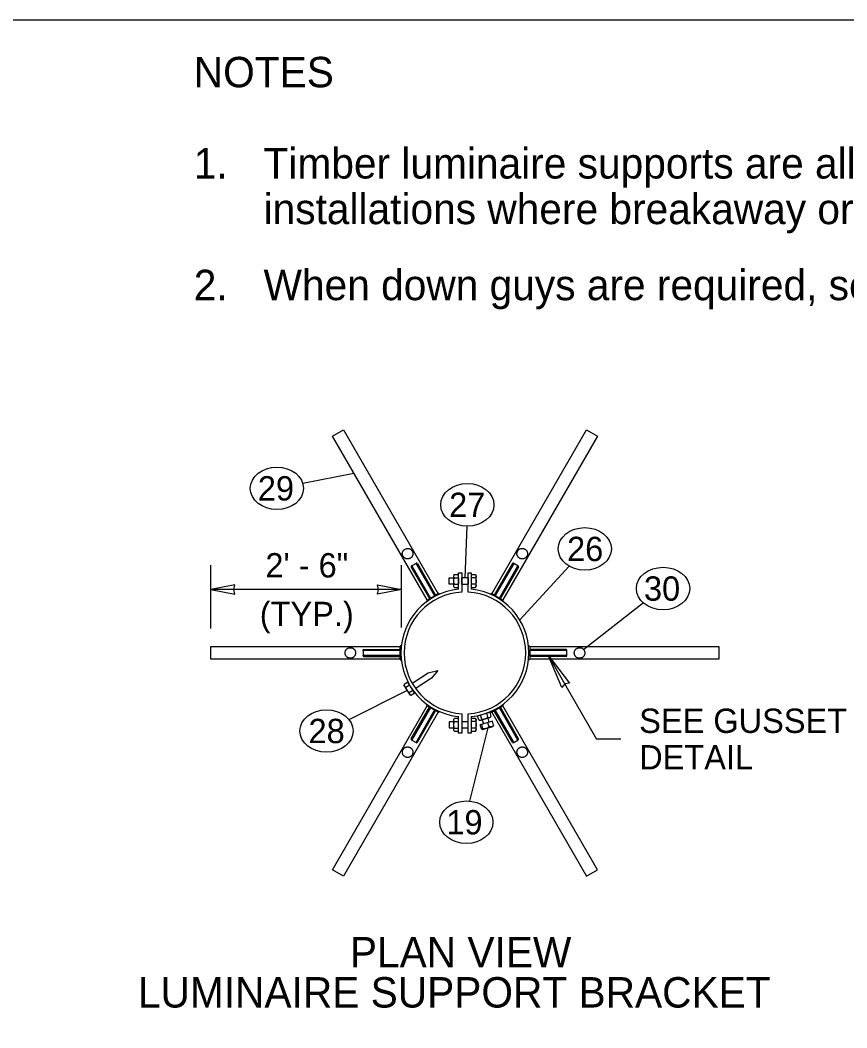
# Model space of a CAD drawing. Extents: x 99862 to 104211, y 98939 to 102076.
# Drawn here: x 102205 to 102749, y 101413 to 102076 of the extents above; entities that cross this region are included whole.
import ezdxf

# ---------------------------------------------------------------- set-up
doc = ezdxf.new("R2010")
doc.units = 0
for name, color, linetype in [('Level 1', 7, 'Continuous'), ('Level 15', 7, 'Continuous'), ('Level 2', 7, 'Continuous'), ('Level 20', 7, 'Continuous'), ('Level 3', 7, 'Continuous'), ('Level 4', 7, 'Continuous'), ('Level 7', 7, 'Continuous'), ('Level 9', 7, 'Continuous')]:
    doc.layers.add(name, color=color, linetype=linetype)

msp = doc.modelspace()

# ---------------------------------------------------------------- linework, layer by layer
at = {"layer": 'Level 1'}
msp.add_lwpolyline([(99862, 99999.5), (103151, 99999.5), (103151, 102075.5), (99862, 102075.5)], close=True, dxfattribs=at)
at = {"layer": 'Level 15'}
for p, q in [((102390.97, 101770.99), (102424.58, 101777.63)), ((102498.77, 101742.78), (102497.63, 101708.74)), ((102330.55, 101675.56), (102330.55, 101717.03)), ((102455.81, 101676.03), (102455.81, 101717.03)), ((102566.08, 101716.5), (102533.67, 101681.12)), ((102455.81, 101701.03), (102330.55, 101701.03)), ((102614.99, 101692.33), (102575.75, 101661.56)), ((102552.44, 101657.85), (102584.22, 101602.81)), ((102421.39, 101615.56), (102459.49, 101634.79)), ((102512.67, 101610.1), (102500.54, 101561.98)), ((102600.22, 101602.81), (102584.22, 101602.81))]:
    msp.add_line(p, q, dxfattribs=at)
for points in [[(102330.55, 101701.03), (102346.28, 101697.94), (102345.55, 101701.03), (102346.28, 101704.11)], [(102455.81, 101701.03), (102440.08, 101697.94), (102440.81, 101701.03), (102440.08, 101704.11)], [(102552.44, 101657.85), (102566.44, 101639.57), (102563.33, 101638.99), (102561.27, 101636.59)]]:
    msp.add_lwpolyline(points, close=True, dxfattribs=at)
at = {"layer": 'Level 2'}
for p, q in [((102493.48, 101701.28), (102493.48, 101712.14)), ((102493.48, 101712.14), (102495.55, 101712.14)), ((102493.48, 101708.76), (102493.48, 101704.61)), ((102495.55, 101712.14), (102495.55, 101699.35)), ((102495.55, 101704.61), (102495.55, 101708.76)), ((102499.7, 101699.35), (102499.7, 101712.14)), ((102499.7, 101712.14), (102501.78, 101712.14)), ((102499.7, 101708.76), (102499.7, 101704.61)), ((102501.78, 101712.14), (102501.78, 101701.28)), ((102493.48, 101704.59), (102493.48, 101704.61)), ((102495.55, 101704.61), (102495.55, 101704.59)), ((102495.55, 101704.61), (102495.55, 101704.59)), ((102493.48, 101606.67), (102493.48, 101617.54)), ((102495.55, 101619.46), (102495.55, 101606.67)), ((102499.7, 101606.67), (102499.7, 101619.46)), ((102501.78, 101617.54), (102501.78, 101606.67)), ((102495.55, 101606.67), (102493.48, 101606.67)), ((102501.78, 101606.67), (102499.7, 101606.67))]:
    msp.add_line(p, q, dxfattribs=at)
for radius, start, end in [(42.07, 95.66048, 264.33952), (42.07, 275.66048, 84.33952), (40, 92.97355, 267.02645), (40, 272.97355, 87.02645)]:
    msp.add_arc((102497.63, 101659.41), radius, start, end, dxfattribs=at)
at = {"layer": 'Level 20'}
for centre in [(102373.98, 101767.64), (102499.24, 101756.78), (102576.43, 101727.79), (102627.93, 101701.75), (102406.59, 101608.08), (102498.57, 101548.07)]:
    msp.add_ellipse(centre, major_axis=(-17.5, 0), ratio=0.8, dxfattribs=at)
at = {"layer": 'Level 3'}
for p, q in [((102465.46, 101718.24), (102462.76, 101716.68)), ((102462.77, 101716.67), (102474.98, 101695.52)), ((102477.68, 101697.07), (102465.46, 101718.24)), ((102529.79, 101718.23), (102517.58, 101697.07)), ((102520.27, 101695.52), (102532.49, 101716.68)), ((102532.49, 101716.68), (102529.8, 101718.24)), ((102455.03, 101660.96), (102430.6, 101660.96)), ((102430.6, 101660.96), (102430.6, 101657.85)), ((102564.65, 101660.96), (102540.22, 101660.96)), ((102564.66, 101657.85), (102564.66, 101660.96)), ((102430.6, 101657.85), (102455.03, 101657.85)), ((102540.22, 101657.85), (102564.66, 101657.85)), ((102474.98, 101623.3), (102462.76, 101602.13)), ((102465.46, 101600.58), (102477.68, 101621.74)), ((102517.58, 101621.74), (102529.8, 101600.58)), ((102532.49, 101602.14), (102520.27, 101623.3)), ((102462.76, 101602.13), (102465.46, 101600.58)), ((102529.8, 101600.58), (102532.49, 101602.13))]:
    msp.add_line(p, q, dxfattribs=at)
at = {"layer": 'Level 4'}
for p, q in [((102410.5, 101802.02), (102417.68, 101806.17)), ((102417.68, 101806.17), (102479.92, 101698.37)), ((102515.33, 101698.37), (102577.57, 101806.17)), ((102577.57, 101806.17), (102584.76, 101802.02)), ((102472.74, 101694.22), (102410.5, 101802.02)), ((102584.76, 101802.02), (102522.52, 101694.22)), ((102330.55, 101655.26), (102330.55, 101663.56)), ((102330.55, 101663.56), (102455.03, 101663.56)), ((102540.22, 101663.56), (102664.7, 101663.56)), ((102664.7, 101663.56), (102664.7, 101655.26)), ((102455.03, 101655.26), (102330.55, 101655.26)), ((102664.7, 101655.26), (102540.22, 101655.26)), ((102410.5, 101516.79), (102472.74, 101624.59)), ((102479.92, 101620.44), (102417.68, 101512.64)), ((102515.33, 101620.44), (102577.57, 101512.64)), ((102584.76, 101516.79), (102522.52, 101624.59)), ((102417.68, 101512.64), (102410.5, 101516.79)), ((102577.57, 101512.64), (102584.76, 101516.79))]:
    msp.add_line(p, q, dxfattribs=at)
for points in [[(102458.22, 101727.67), (102458, 101727.54), (102457.81, 101727.4), (102457.45, 101727.09), (102457.29, 101726.92), (102456.86, 101726.37), (102456.67, 101725.97), (102456.45, 101725.14), (102456.42, 101724.71), (102456.52, 101724.06), (102456.57, 101723.83), (102456.72, 101723.39), (102456.83, 101723.17), (102457.07, 101722.75), (102457.21, 101722.55), (102457.52, 101722.19), (102457.68, 101722.04), (102458.03, 101721.76), (102458.21, 101721.64), (102458.6, 101721.45), (102458.79, 101721.38), (102459.41, 101721.21), (102459.86, 101721.17), (102460.55, 101721.27), (102460.78, 101721.32), (102461.23, 101721.48), (102461.45, 101721.58), (102461.87, 101721.82), (102462.07, 101721.96), (102462.43, 101722.28), (102462.59, 101722.45), (102462.88, 101722.81), (102463, 101723.01), (102463.19, 101723.4), (102463.27, 101723.61), (102463.43, 101724.23), (102463.46, 101724.66), (102463.36, 101725.31), (102463.31, 101725.53), (102463.16, 101725.98), (102463.05, 101726.2), (102462.81, 101726.62), (102462.67, 101726.82), (102462.36, 101727.18), (102462.2, 101727.33), (102461.85, 101727.6), (102461.67, 101727.72), (102461.29, 101727.91), (102461.09, 101727.99), (102460.67, 101728.1), (102460.46, 101728.14), (102460.02, 101728.17), (102459.79, 101728.16), (102459.11, 101728.07), (102458.64, 101727.91), (102458.22, 101727.67)], [(102537.04, 101727.67), (102536.83, 101727.79), (102536.6, 101727.89), (102536.15, 101728.04), (102535.92, 101728.1), (102535.24, 101728.19), (102534.79, 101728.16), (102533.97, 101727.94), (102533.58, 101727.74), (102533.06, 101727.34), (102532.89, 101727.18), (102532.59, 101726.82), (102532.45, 101726.62), (102532.2, 101726.2), (102532.1, 101725.98), (102531.94, 101725.54), (102531.89, 101725.32), (102531.83, 101724.88), (102531.82, 101724.66), (102531.84, 101724.23), (102531.88, 101724.02), (102532.04, 101723.4), (102532.24, 101723), (102532.66, 101722.45), (102532.82, 101722.28), (102533.18, 101721.96), (102533.38, 101721.82), (102533.8, 101721.58), (102534.03, 101721.47), (102534.48, 101721.32), (102534.71, 101721.27), (102535.17, 101721.21), (102535.39, 101721.2), (102535.83, 101721.23), (102536.05, 101721.26), (102536.66, 101721.43), (102537.05, 101721.62), (102537.57, 101722.03), (102537.74, 101722.19), (102538.04, 101722.54), (102538.18, 101722.74), (102538.43, 101723.17), (102538.53, 101723.38), (102538.68, 101723.83), (102538.74, 101724.05), (102538.8, 101724.49), (102538.81, 101724.71), (102538.79, 101725.13), (102538.75, 101725.34), (102538.64, 101725.76), (102538.57, 101725.96), (102538.37, 101726.36), (102538.25, 101726.55), (102537.83, 101727.1), (102537.46, 101727.42), (102537.04, 101727.67)], [(102418.81, 101659.41), (102418.81, 101659.16), (102418.83, 101658.92), (102418.92, 101658.45), (102418.99, 101658.22), (102419.25, 101657.58), (102419.5, 101657.21), (102420.11, 101656.61), (102420.47, 101656.37), (102421.08, 101656.13), (102421.3, 101656.06), (102421.76, 101655.97), (102422.01, 101655.95), (102422.49, 101655.95), (102422.73, 101655.97), (102423.2, 101656.06), (102423.41, 101656.12), (102423.83, 101656.29), (102424.02, 101656.39), (102424.38, 101656.63), (102424.54, 101656.76), (102425, 101657.21), (102425.25, 101657.58), (102425.51, 101658.22), (102425.58, 101658.45), (102425.67, 101658.92), (102425.7, 101659.16), (102425.7, 101659.65), (102425.67, 101659.89), (102425.58, 101660.36), (102425.51, 101660.59), (102425.34, 101661.02), (102425.23, 101661.21), (102424.99, 101661.58), (102424.85, 101661.75), (102424.39, 101662.2), (102424.03, 101662.44), (102423.42, 101662.68), (102423.2, 101662.75), (102422.74, 101662.84), (102422.5, 101662.86), (102422.01, 101662.86), (102421.77, 101662.84), (102421.31, 101662.75), (102421.09, 101662.69), (102420.68, 101662.52), (102420.49, 101662.42), (102420.13, 101662.19), (102419.96, 101662.05), (102419.66, 101661.75), (102419.52, 101661.58), (102419.27, 101661.22), (102419.17, 101661.02), (102418.9, 101660.38), (102418.81, 101659.9), (102418.81, 101659.41)], [(102576.45, 101659.41), (102576.45, 101659.65), (102576.42, 101659.89), (102576.33, 101660.36), (102576.26, 101660.59), (102576, 101661.23), (102575.75, 101661.6), (102575.14, 101662.2), (102574.79, 101662.44), (102574.17, 101662.68), (102573.95, 101662.75), (102573.49, 101662.84), (102573.25, 101662.86), (102572.76, 101662.86), (102572.52, 101662.84), (102572.06, 101662.75), (102571.84, 101662.69), (102571.43, 101662.52), (102571.23, 101662.42), (102570.88, 101662.19), (102570.71, 101662.05), (102570.26, 101661.6), (102570, 101661.23), (102569.74, 101660.59), (102569.67, 101660.36), (102569.58, 101659.89), (102569.56, 101659.65), (102569.56, 101659.16), (102569.58, 101658.92), (102569.67, 101658.45), (102569.74, 101658.22), (102569.92, 101657.8), (102570.02, 101657.6), (102570.27, 101657.23), (102570.41, 101657.06), (102570.86, 101656.61), (102571.22, 101656.37), (102571.83, 101656.13), (102572.05, 101656.06), (102572.51, 101655.97), (102572.76, 101655.95), (102573.24, 101655.95), (102573.48, 101655.97), (102573.95, 101656.06), (102574.17, 101656.13), (102574.58, 101656.29), (102574.77, 101656.39), (102575.13, 101656.62), (102575.29, 101656.76), (102575.6, 101657.06), (102575.74, 101657.23), (102575.98, 101657.59), (102576.09, 101657.79), (102576.35, 101658.44), (102576.45, 101658.92), (102576.45, 101659.41)], [(102458.22, 101591.14), (102458.43, 101591.02), (102458.65, 101590.92), (102459.1, 101590.77), (102459.33, 101590.71), (102460.02, 101590.62), (102460.46, 101590.65), (102461.29, 101590.88), (102461.67, 101591.07), (102462.19, 101591.48), (102462.36, 101591.64), (102462.67, 101591.99), (102462.81, 101592.19), (102463.05, 101592.61), (102463.15, 101592.83), (102463.31, 101593.28), (102463.36, 101593.5), (102463.43, 101593.93), (102463.43, 101594.15), (102463.41, 101594.58), (102463.38, 101594.79), (102463.21, 101595.41), (102463.02, 101595.81), (102462.59, 101596.36), (102462.43, 101596.54), (102462.07, 101596.85), (102461.87, 101596.99), (102461.45, 101597.24), (102461.23, 101597.34), (102460.78, 101597.49), (102460.55, 101597.55), (102460.09, 101597.61), (102459.86, 101597.61), (102459.42, 101597.59), (102459.21, 101597.55), (102458.59, 101597.38), (102458.2, 101597.19), (102457.68, 101596.78), (102457.52, 101596.62), (102457.21, 101596.27), (102457.07, 101596.07), (102456.83, 101595.65), (102456.73, 101595.43), (102456.57, 101594.98), (102456.52, 101594.76), (102456.45, 101594.33), (102456.44, 101594.11), (102456.47, 101593.68), (102456.5, 101593.47), (102456.61, 101593.05), (102456.69, 101592.85), (102456.88, 101592.46), (102457, 101592.26), (102457.42, 101591.71), (102457.79, 101591.39), (102458.22, 101591.14)], [(102537.04, 101591.14), (102537.25, 101591.27), (102537.45, 101591.41), (102537.81, 101591.72), (102537.97, 101591.9), (102538.39, 101592.44), (102538.59, 101592.85), (102538.81, 101593.67), (102538.83, 101594.1), (102538.74, 101594.75), (102538.69, 101594.98), (102538.53, 101595.42), (102538.43, 101595.64), (102538.19, 101596.07), (102538.05, 101596.26), (102537.74, 101596.62), (102537.57, 101596.78), (102537.23, 101597.05), (102537.04, 101597.17), (102536.66, 101597.36), (102536.46, 101597.44), (102535.84, 101597.6), (102535.4, 101597.64), (102534.71, 101597.55), (102534.48, 101597.49), (102534.02, 101597.34), (102533.8, 101597.23), (102533.38, 101596.99), (102533.18, 101596.85), (102532.82, 101596.54), (102532.66, 101596.36), (102532.38, 101596), (102532.26, 101595.81), (102532.06, 101595.41), (102531.99, 101595.21), (102531.82, 101594.59), (102531.8, 101594.16), (102531.89, 101593.5), (102531.94, 101593.28), (102532.1, 101592.84), (102532.2, 101592.61), (102532.44, 101592.19), (102532.58, 101592), (102532.89, 101591.64), (102533.06, 101591.48), (102533.4, 101591.21), (102533.59, 101591.09), (102533.97, 101590.9), (102534.17, 101590.82), (102534.58, 101590.71), (102534.8, 101590.67), (102535.23, 101590.64), (102535.46, 101590.65), (102536.15, 101590.74), (102536.61, 101590.9), (102537.04, 101591.14)]]:
    msp.add_open_spline(points, degree=3, dxfattribs=at)
at = {"layer": 'Level 7'}
for p, q in [((102487.19, 101704.63), (102487.19, 101708.74)), ((102487.19, 101708.74), (102490.16, 101708.74)), ((102490.7, 101710.85), (102490.16, 101710.23)), ((102490.16, 101710.23), (102490.16, 101703.14)), ((102493.48, 101710.85), (102490.7, 101710.85)), ((102490.7, 101708.77), (102493.48, 101708.77)), ((102499.7, 101708.74), (102495.55, 101708.74)), ((102504.55, 101710.85), (102501.78, 101710.85)), ((102504.55, 101708.77), (102501.78, 101708.77)), ((102505.09, 101710.23), (102504.55, 101710.85)), ((102505.09, 101703.14), (102505.09, 101710.23)), ((102490.16, 101704.61), (102487.19, 101704.61)), ((102490.16, 101703.14), (102490.7, 101702.52)), ((102490.7, 101704.6), (102493.48, 101704.6)), ((102490.7, 101702.52), (102493.48, 101702.52)), ((102493.48, 101702.52), (102493.48, 101702.5)), ((102495.55, 101704.61), (102499.7, 101704.61)), ((102504.55, 101704.6), (102501.78, 101704.6)), ((102501.78, 101702.52), (102504.55, 101702.52)), ((102504.55, 101702.52), (102505.09, 101703.14)), ((102472.72, 101694.21), (102479.94, 101698.38)), ((102515.32, 101698.38), (102522.53, 101694.21)), ((102455.03, 101655.24), (102455.03, 101663.57)), ((102540.22, 101663.57), (102540.22, 101655.24)), ((102460.02, 101640.09), (102457.68, 101638.59)), ((102464.53, 101633.09), (102460.02, 101640.09)), ((102457.68, 101638.55), (102457.57, 101637.77)), ((102457.57, 101637.77), (102461.41, 101631.82)), ((102458.79, 101636.88), (102461.12, 101638.39)), ((102461.04, 101633.38), (102463.38, 101634.89)), ((102461.41, 101631.82), (102462.15, 101631.6)), ((102462.2, 101631.59), (102464.53, 101633.09)), ((102479.94, 101620.43), (102472.72, 101624.6)), ((102505.93, 101617.96), (102513.91, 101620.37)), ((102513.91, 101620.37), (102514.71, 101617.72)), ((102515.32, 101620.43), (102522.53, 101624.6)), ((102487.19, 101614.2), (102487.19, 101614.18)), ((102487.19, 101614.2), (102487.19, 101614.18)), ((102490.16, 101614.2), (102487.19, 101614.2)), ((102487.19, 101614.18), (102487.19, 101610.07)), ((102487.19, 101614.18), (102487.19, 101610.07)), ((102490.7, 101616.29), (102490.16, 101615.67)), ((102490.16, 101615.67), (102490.16, 101608.58)), ((102493.48, 101616.29), (102490.7, 101616.29)), ((102490.7, 101614.21), (102493.48, 101614.21)), ((102499.7, 101614.2), (102495.55, 101614.2)), ((102504.55, 101616.29), (102501.78, 101616.29)), ((102504.55, 101614.21), (102501.78, 101614.21)), ((102505.09, 101615.67), (102504.55, 101616.29)), ((102505.09, 101608.58), (102505.09, 101615.67)), ((102506.74, 101615.31), (102505.93, 101617.96)), ((102507.49, 101614.97), (102506.74, 101615.31)), ((102514.27, 101617.02), (102507.49, 101614.97)), ((102515.69, 101614.48), (102507.72, 101612.07)), ((102508.73, 101615.91), (102507.93, 101618.56)), ((102508.92, 101615.4), (102509.74, 101612.68)), ((102512.72, 101617.12), (102511.92, 101619.77)), ((102513.49, 101610.89), (102512.68, 101613.55)), ((102513.67, 101613.87), (102512.85, 101616.59)), ((102514.71, 101617.72), (102514.27, 101617.02)), ((102516.5, 101611.82), (102515.69, 101614.48)), ((102487.19, 101610.07), (102487.19, 101610.07)), ((102487.19, 101610.07), (102490.16, 101610.07)), ((102490.16, 101608.58), (102490.7, 101607.96)), ((102490.7, 101610.04), (102493.48, 101610.04)), ((102490.7, 101607.96), (102493.48, 101607.96)), ((102495.55, 101610.07), (102499.7, 101610.07)), ((102504.55, 101610.04), (102501.78, 101610.04)), ((102501.78, 101607.96), (102504.55, 101607.96)), ((102504.55, 101607.96), (102505.09, 101608.58)), ((102508.52, 101609.41), (102507.72, 101612.07)), ((102508.52, 101609.41), (102509.28, 101609.07)), ((102509.5, 101609.68), (102508.7, 101612.34)), ((102509.28, 101609.07), (102516.06, 101611.12)), ((102516.06, 101611.12), (102516.5, 101611.82))]:
    msp.add_line(p, q, dxfattribs=at)
msp.add_lwpolyline([(102463.33, 101639.72), (102473.42, 101646.22), (102479.78, 101647.89), (102475.64, 101642.78), (102465.56, 101636.27)], dxfattribs=at)
for centre, start, end in [((102472.98, 101693.76), 120, 239.26152), ((102480.2, 101697.93), 0.74038, 120), ((102515.06, 101697.93), 60, 179.25655), ((102522.27, 101693.76), 300.74736, 60), ((102455.55, 101663.57), 60.73742, 180), ((102539.7, 101663.57), 0, 119.25359), ((102455.55, 101655.24), 180, 299.26353), ((102539.7, 101655.24), 240.74736, 0), ((102472.98, 101625.05), 120.74736, 240), ((102480.2, 101620.88), 240, 359.25359), ((102515.06, 101620.88), 180.74736, 300), ((102522.27, 101625.05), 300, 59.25359)]:
    msp.add_arc(centre, 0.521, start, end, dxfattribs=at)
for points in [[(102490.7, 101708.77), (102490.42, 101709.1), (102490.22, 101709.45), (102490.22, 101709.99), (102490.27, 101710.17), (102490.44, 101710.52), (102490.56, 101710.69), (102490.7, 101710.85)], [(102490.7, 101704.6), (102490.56, 101704.93), (102490.44, 101705.27), (102490.27, 101705.97), (102490.22, 101706.32), (102490.22, 101707.05), (102490.27, 101707.4), (102490.44, 101708.1), (102490.56, 101708.44), (102490.7, 101708.77)], [(102504.55, 101710.85), (102504.69, 101710.69), (102504.82, 101710.52), (102504.99, 101710.17), (102505.04, 101709.99), (102505.04, 101709.45), (102504.84, 101709.1), (102504.55, 101708.77)], [(102504.55, 101708.77), (102504.69, 101708.44), (102504.82, 101708.1), (102504.99, 101707.4), (102505.04, 101707.05), (102505.04, 101706.32), (102504.99, 101705.97), (102504.82, 101705.27), (102504.69, 101704.93), (102504.55, 101704.6)], [(102490.7, 101702.52), (102490.42, 101702.85), (102490.22, 101703.2), (102490.22, 101703.74), (102490.27, 101703.92), (102490.44, 101704.27), (102490.56, 101704.44), (102490.7, 101704.6)], [(102504.55, 101704.6), (102504.69, 101704.44), (102504.82, 101704.27), (102504.99, 101703.92), (102505.04, 101703.74), (102505.04, 101703.2), (102504.84, 101702.85), (102504.55, 101702.52)], [(102458.79, 101636.88), (102458.58, 101636.94), (102458.39, 101637.01), (102458.06, 101637.2), (102457.92, 101637.33), (102457.64, 101637.76), (102457.62, 101638.16), (102457.68, 101638.59)], [(102461.04, 101633.38), (102460.75, 101633.58), (102460.46, 101633.8), (102459.94, 101634.29), (102459.7, 101634.57), (102459.31, 101635.18), (102459.16, 101635.5), (102458.93, 101636.17), (102458.84, 101636.53), (102458.79, 101636.88)], [(102462.2, 101631.59), (102461.99, 101631.65), (102461.8, 101631.73), (102461.46, 101631.94), (102461.32, 101632.07), (102461.02, 101632.53), (102460.99, 101632.94), (102461.04, 101633.38)], [(102490.7, 101614.21), (102490.42, 101614.54), (102490.22, 101614.89), (102490.22, 101615.43), (102490.27, 101615.61), (102490.44, 101615.96), (102490.56, 101616.13), (102490.7, 101616.29)], [(102490.7, 101610.04), (102490.56, 101610.37), (102490.44, 101610.71), (102490.27, 101611.41), (102490.22, 101611.76), (102490.22, 101612.49), (102490.27, 101612.84), (102490.44, 101613.54), (102490.56, 101613.88), (102490.7, 101614.21)], [(102504.55, 101616.29), (102504.69, 101616.13), (102504.82, 101615.96), (102504.99, 101615.61), (102505.04, 101615.43), (102505.04, 101614.89), (102504.84, 101614.54), (102504.55, 101614.21)], [(102504.55, 101614.21), (102504.69, 101613.88), (102504.82, 101613.54), (102504.99, 101612.84), (102505.04, 101612.49), (102505.04, 101611.76), (102504.99, 101611.41), (102504.82, 101610.71), (102504.69, 101610.37), (102504.55, 101610.04)], [(102506.74, 101615.31), (102506.94, 101615.22), (102507.13, 101615.15), (102507.51, 101615.09), (102507.7, 101615.09), (102508.22, 101615.25), (102508.5, 101615.54), (102508.73, 101615.91)], [(102508.73, 101615.91), (102509.09, 101615.87), (102509.45, 101615.85), (102510.17, 101615.89), (102510.52, 101615.94), (102511.21, 101616.15), (102511.54, 101616.3), (102512.15, 101616.67), (102512.44, 101616.88), (102512.72, 101617.12)], [(102512.72, 101617.12), (102512.92, 101617.03), (102513.11, 101616.96), (102513.5, 101616.9), (102513.68, 101616.9), (102514.2, 101617.06), (102514.48, 101617.35), (102514.71, 101617.72)], [(102490.7, 101607.96), (102490.42, 101608.29), (102490.22, 101608.64), (102490.22, 101609.18), (102490.27, 101609.36), (102490.44, 101609.71), (102490.56, 101609.88), (102490.7, 101610.04)], [(102504.55, 101610.04), (102504.69, 101609.88), (102504.82, 101609.71), (102504.99, 101609.36), (102505.04, 101609.18), (102505.04, 101608.64), (102504.84, 101608.29), (102504.55, 101607.96)], [(102509.5, 101609.69), (102509.44, 101609.6), (102509.39, 101609.53), (102509.25, 101609.4), (102509.17, 101609.36), (102508.92, 101609.28), (102508.72, 101609.32), (102508.52, 101609.41)], [(102509.5, 101609.68), (102509.85, 101609.64), (102510.22, 101609.62), (102510.93, 101609.66), (102511.28, 101609.72), (102511.98, 101609.93), (102512.3, 101610.08), (102512.92, 101610.44), (102513.21, 101610.66), (102513.49, 101610.89)], [(102516.5, 101611.82), (102516.38, 101611.64), (102516.25, 101611.47), (102515.97, 101611.21), (102515.81, 101611.11), (102515.3, 101610.95), (102514.58, 101610.7), (102513.49, 101610.89)]]:
    msp.add_open_spline(points, degree=3, dxfattribs=at)
at = {"layer": 'Level 9'}
for p, q in [((102462.37, 101715.9), (102474.35, 101695.15)), ((102466.33, 101718.19), (102478.31, 101697.44)), ((102528.92, 101718.19), (102516.94, 101697.44)), ((102532.89, 101715.9), (102520.91, 101695.15)), ((102472.72, 101694.21), (102479.94, 101698.38)), ((102515.32, 101698.38), (102515.33, 101698.37)), ((102515.32, 101698.38), (102515.32, 101698.38)), ((102515.32, 101698.38), (102522.53, 101694.21)), ((102431.07, 101661.69), (102455.03, 101661.69)), ((102564.18, 101661.69), (102540.22, 101661.69)), ((102431.07, 101657.12), (102455.03, 101657.12)), ((102564.18, 101657.12), (102540.22, 101657.12)), ((102462.37, 101602.91), (102474.35, 101623.66)), ((102466.33, 101600.62), (102478.31, 101621.37)), ((102515.33, 101620.44), (102515.32, 101620.43)), ((102528.92, 101600.62), (102516.94, 101621.37)), ((102532.89, 101602.91), (102520.91, 101623.66)), ((102522.53, 101624.6), (102522.52, 101624.59)), ((102522.53, 101624.6), (102522.53, 101624.6))]:
    msp.add_line(p, q, dxfattribs=at)
for centre, start, end in [((102462.82, 101716.16), 120, 209.9708), ((102462.82, 101716.16), 96.14627, 120), ((102465.88, 101717.93), 120, 143.85373), ((102465.88, 101717.93), 30.0292, 120), ((102529.37, 101717.93), 60, 149.9708), ((102529.37, 101717.93), 36.14627, 60), ((102532.43, 101716.16), 60, 83.85373), ((102532.43, 101716.16), 330.0292, 60), ((102472.98, 101693.76), 120, 239.25359), ((102480.2, 101697.93), 0.74736, 120), ((102515.06, 101697.93), 60, 179.25359), ((102431.07, 101661.17), 90.0292, 180), ((102431.07, 101661.17), 180, 203.85373), ((102455.55, 101663.57), 60.74736, 180), ((102564.18, 101661.17), 0, 89.9708), ((102564.18, 101661.17), 336.14627, 0), ((102431.07, 101657.64), 156.14627, 180), ((102431.07, 101657.64), 180, 269.9708), ((102455.55, 101655.24), 180, 299.25359), ((102564.18, 101657.64), 270.0292, 0), ((102564.18, 101657.64), 0, 23.85373), ((102462.82, 101602.65), 150.0292, 240), ((102462.82, 101602.65), 240, 263.85373), ((102465.88, 101600.88), 216.14627, 240), ((102465.88, 101600.88), 240, 329.9708), ((102529.37, 101600.88), 210.0292, 300), ((102529.37, 101600.88), 300, 323.85373), ((102532.43, 101602.65), 276.14627, 300), ((102532.43, 101602.65), 300, 29.9708)]:
    msp.add_arc(centre, 0.521, start, end, dxfattribs=at)

# ---------------------------------------------------------------- texts
at = {"layer": 'Level 20'}
for s, height, p in [('NOTES', 20, (102319.29, 102031.36)), ('1.', 20, (102319.29, 101971.36)), ('Timber luminaire supports are allowed only for temporary', 20, (102365.2, 101971.36)), ('installations where breakaway or Slip Bases are not required.', 20, (102365.2, 101941.36)), ('2.', 20, (102319.29, 101891.36)), ('When down guys are required, see', 20, (102365.2, 101891.36)), ('29', 16, (102361.42, 101759.64)), ('27', 16, (102487.21, 101748.78)), ('26', 16, (102564.8, 101719.79)), ('2\' - 6"', 16, (102366.39, 101709.03)), ('30', 16, (102615.38, 101693.75)), ('(TYP.)', 16, (102362.7, 101677.03)), ('SEE GUSSET', 16, (102612.22, 101606.8)), ('28', 16, (102394.76, 101600.08)), ('DETAIL', 16, (102612.22, 101582.8)), ('19', 16, (102485.41, 101540.07)), ('PLAN VIEW', 20, (102421.97, 101452.64)), ('LUMINAIRE SUPPORT BRACKET', 20, (102282.55, 101426.23))]:
    msp.add_text(s, height=height, dxfattribs=at).set_placement(p)

doc.saveas('drawing.dxf')
